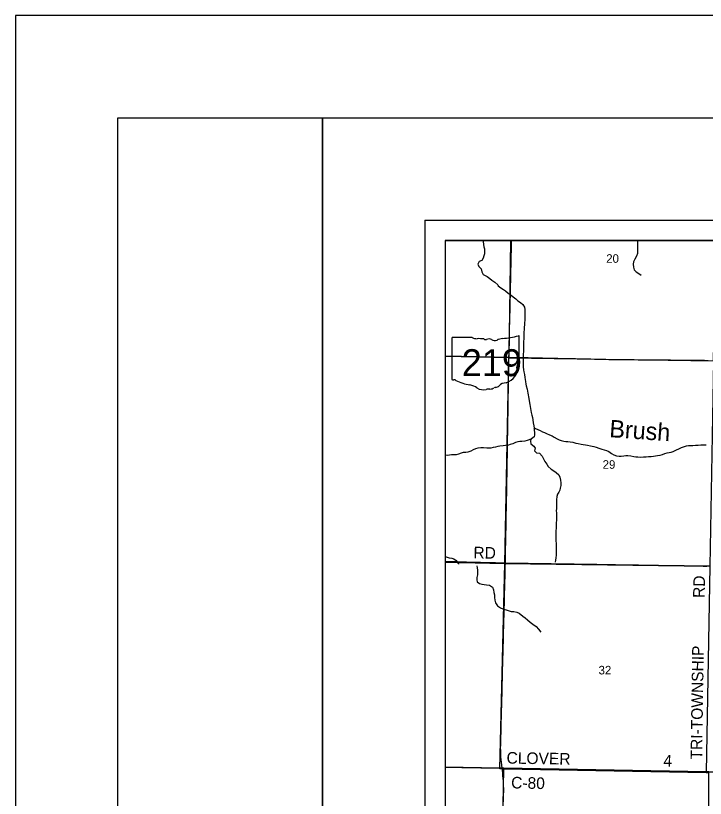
# Model space of a CAD drawing. Extents: x -11.1 to 34, y -3.9 to 22.
# Drawn here: x 0 to 3.372, y 18.172 to 22 of the extents above; entities that cross this region are included whole.
import ezdxf

# ---------------------------------------------------------------- set-up
doc = ezdxf.new("R2010")
doc.units = 0
for name, color, linetype in [('GM_X_Corporation', 7, 'Continuous'), ('GM_X_County_Road', 7, 'Continuous'), ('GM_X_County_Road_Text', 7, 'Continuous'), ('GM_X_Minor_River', 7, 'Continuous'), ('GM_X_Minor_River_Text', 7, 'Continuous'), ('GM_X_Section_Text', 7, 'Continuous'), ('GM_X_State_Location', 7, 'Continuous'), ('GM_X_State_Route', 7, 'Continuous'), ('GM_X_State_Shield', 7, 'Continuous'), ('GM_X_Township_Road_Text', 7, 'Continuous'), ('SH_Border', 7, 'Continuous'), ('SH_Cut_Line', 7, 'Continuous'), ('SH_Data', 7, 'Continuous')]:
    doc.layers.add(name, color=color, linetype=linetype)

msp = doc.modelspace()

# ---------------------------------------------------------------- linework, layer by layer
at = {"layer": 'GM_X_Corporation'}
for points in [[(8.9, 20.9), (2.1, 20.9), (2.1, 14.1), (7.332, 14.1)], [(7.452, 20.9), (2.1, 20.9), (2.1, 18.3243), (2.3663, 18.3195), (2.386, 18.3192), (3.3765, 18.301), (3.3885, 18.301), (4.3933, 18.2849), (4.8079, 18.2783), (5.3973, 18.2661), (6.2873, 18.2553), (6.3214, 18.2549), (6.5234, 18.2515), (7.399, 18.2383)], [(7.399, 18.2383), (6.5234, 18.2515), (6.3214, 18.2549), (6.2873, 18.2553), (5.3973, 18.2661), (4.8079, 18.2783), (4.3933, 18.2849), (3.3885, 18.301), (3.3765, 18.301), (2.386, 18.3192), (2.3663, 18.3195), (2.1, 18.3243), (2.1, 15.3106)]]:
    msp.add_lwpolyline(points, dxfattribs=at)
for points in [[(3.4231, 20.9), (2.4189, 20.9), (2.4116, 20.3267), (3.4122, 20.3123)], [(2.1, 20.3321), (2.1, 19.327), (2.3914, 19.3197), (2.4116, 20.3267)], [(3.4122, 20.3123), (3.3936, 19.3072), (2.3914, 19.3197), (2.4116, 20.3267)], [(2.3914, 19.3197), (3.3936, 19.3072), (3.3764, 18.2972), (2.3861, 18.3151), (2.3675, 18.3155)], [(2.3861, 18.3151), (3.3764, 18.2972), (3.3877, 18.2966), (3.3852, 17.301), (2.3686, 17.3282)]]:
    msp.add_lwpolyline(points, close=True, dxfattribs=at)
at = {"layer": 'GM_X_County_Road'}
for points in [[(2.1, 19.3307), (2.104, 19.3306), (2.1226, 19.3301), (2.1413, 19.3296), (2.1544, 19.3293), (2.1675, 19.3289), (2.1862, 19.3284), (2.2048, 19.3279), (2.22, 19.3275), (2.2351, 19.3271), (2.2538, 19.3267), (2.2724, 19.3263), (2.291, 19.3259), (2.3096, 19.3255), (2.3282, 19.3251), (2.346, 19.3246), (2.3637, 19.3242), (2.3758, 19.3238), (2.3879, 19.3235), (2.3944, 19.3229), (2.413, 19.3227), (2.4317, 19.3224), (2.4503, 19.3221), (2.4689, 19.3218), (2.4876, 19.3215), (2.5062, 19.3213), (2.5249, 19.321), (2.5435, 19.3207), (2.5621, 19.3204), (2.5808, 19.3201), (2.5994, 19.3199), (2.6181, 19.3196), (2.6367, 19.3193), (2.6554, 19.319), (2.674, 19.3187), (2.6926, 19.3185), (2.7113, 19.3182), (2.7299, 19.3179), (2.7486, 19.3176), (2.7672, 19.3173), (2.7858, 19.317), (2.8045, 19.3168), (2.8231, 19.3165), (2.8418, 19.3162), (2.8604, 19.3159), (2.8781, 19.3156), (2.8958, 19.3154), (2.9144, 19.3151), (2.933, 19.3148), (2.9517, 19.3145), (2.9703, 19.3142), (2.989, 19.3139), (3.0076, 19.3136), (3.0263, 19.3133), (3.0449, 19.313), (3.0635, 19.3127), (3.0822, 19.3124), (3.1008, 19.3121), (3.1195, 19.3118), (3.1381, 19.3115), (3.1567, 19.3112), (3.1754, 19.3109), (3.194, 19.3106), (3.2127, 19.3103), (3.2313, 19.31), (3.2499, 19.3097), (3.2686, 19.3094), (3.2872, 19.3091), (3.3059, 19.3088), (3.3245, 19.3085), (3.3431, 19.3082), (3.3618, 19.3079), (3.3795, 19.3076)], [(2.1, 18.3245), (2.1071, 18.3243), (2.1257, 18.324), (2.1443, 18.3237), (2.163, 18.3234), (2.1816, 18.3231), (2.2003, 18.3227), (2.2189, 18.3224), (2.2376, 18.3221), (2.2562, 18.3218), (2.2748, 18.3215), (2.2935, 18.3211), (2.3121, 18.3208), (2.3308, 18.3205), (2.3494, 18.3202), (2.3639, 18.3199), (2.3785, 18.3197), (2.3971, 18.3193), (2.4158, 18.319), (2.4344, 18.3186), (2.453, 18.3183), (2.4717, 18.3179), (2.4903, 18.3175), (2.5089, 18.3172), (2.5276, 18.3168), (2.5462, 18.3165), (2.5648, 18.3161), (2.5835, 18.3158), (2.6021, 18.3154), (2.6207, 18.3151), (2.6394, 18.3147), (2.658, 18.3144), (2.6766, 18.314), (2.6953, 18.3137), (2.7139, 18.3133), (2.7325, 18.313), (2.7512, 18.3126), (2.7698, 18.3123), (2.7885, 18.3119), (2.8071, 18.3116), (2.8257, 18.3112), (2.8444, 18.3109), (2.8585, 18.3106), (2.8726, 18.3103), (2.8913, 18.31), (2.9099, 18.3096), (2.9285, 18.3093), (2.9472, 18.3089), (2.9658, 18.3085), (2.9844, 18.3082), (3.0031, 18.3078), (3.0217, 18.3075), (3.0403, 18.3071), (3.059, 18.3067), (3.0776, 18.3064), (3.0963, 18.306), (3.1149, 18.3056), (3.1335, 18.3053), (3.1522, 18.3049), (3.1708, 18.3045), (3.1894, 18.3042), (3.2081, 18.3038), (3.2267, 18.3035), (3.2453, 18.3031), (3.264, 18.3027), (3.2826, 18.3024), (3.3012, 18.302), (3.3199, 18.3016), (3.3385, 18.3013), (3.3561, 18.3009), (3.3736, 18.3006)]]:
    msp.add_lwpolyline(points, dxfattribs=at)
at = {"layer": 'GM_X_Minor_River'}
msp.add_line((3.0391, 20.9), (3.0399, 20.8925), dxfattribs=at)
for points in [[(2.2862, 20.9), (2.2864, 20.896), (2.2879, 20.8812), (2.2895, 20.8697), (2.2915, 20.8598), (2.293, 20.845), (2.2927, 20.8347), (2.2883, 20.8246), (2.2853, 20.8132), (2.2789, 20.802), (2.2659, 20.7978), (2.2602, 20.7846), (2.2641, 20.7735), (2.2752, 20.7611), (2.2786, 20.7469), (2.2851, 20.7342), (2.2952, 20.7287), (2.305, 20.7235), (2.3177, 20.7148), (2.3282, 20.7069), (2.342, 20.6963), (2.3568, 20.683)], [(3.0399, 20.8925), (3.04, 20.8822), (3.0397, 20.8727), (3.0395, 20.8628), (3.0399, 20.8499), (3.0399, 20.8358), (3.0358, 20.823), (3.0266, 20.8085), (3.0213, 20.7953), (3.0191, 20.784), (3.0199, 20.7691), (3.0245, 20.7561), (3.0337, 20.7464), (3.0461, 20.7384), (3.0576, 20.7301)], [(2.3568, 20.683), (2.3594, 20.6786), (2.3717, 20.6684), (2.3848, 20.6609), (2.3957, 20.6535), (2.4083, 20.6433), (2.4225, 20.6324), (2.4326, 20.6253), (2.4456, 20.6144), (2.4557, 20.6058), (2.468, 20.5964), (2.4799, 20.587), (2.4872, 20.574), (2.4888, 20.5625), (2.4901, 20.55), (2.4902, 20.5393), (2.4897, 20.5192), (2.4891, 20.5082), (2.4881, 20.4984), (2.4872, 20.4889), (2.4861, 20.4748), (2.4858, 20.4642), (2.4852, 20.4521), (2.4846, 20.4407), (2.4839, 20.4305), (2.4831, 20.3948), (2.4833, 20.3838), (2.4833, 20.3686), (2.4826, 20.3564), (2.482, 20.3451), (2.4813, 20.3318), (2.4811, 20.3196), (2.4815, 20.3056), (2.4812, 20.2938), (2.4814, 20.2828), (2.4829, 20.2683), (2.485, 20.2576), (2.4877, 20.2447), (2.4897, 20.2306), (2.4906, 20.2203), (2.4919, 20.2108), (2.4946, 20.1982), (2.4967, 20.1886), (2.5001, 20.173), (2.5025, 20.1634), (2.5046, 20.1528), (2.5085, 20.1268), (2.5106, 20.1162), (2.5136, 20.0982), (2.5156, 20.0879), (2.5169, 20.0777), (2.519, 20.0681), (2.521, 20.0582), (2.5238, 20.046), (2.5262, 20.0345), (2.5282, 20.0238), (2.5309, 20.0082), (2.5332, 19.9941), (2.5345, 19.9819), (2.535, 19.972), (2.5359, 19.961), (2.5364, 19.9492), (2.535, 19.9394), (2.5227, 19.9298), (2.5108, 19.9255), (2.5001, 19.9223), (2.4887, 19.9192), (2.475, 19.9176), (2.4655, 19.9174), (2.4548, 19.9157), (2.4434, 19.9122), (2.4303, 19.9064), (2.4185, 19.9025), (2.409, 19.8997), (2.3949, 19.897), (2.3827, 19.8961), (2.3664, 19.8949), (2.3568, 19.8932), (2.3458, 19.8901), (2.3354, 19.8869), (2.3233, 19.8845), (2.3138, 19.8836), (2.3031, 19.8838), (2.288, 19.8853), (2.2751, 19.8856), (2.2603, 19.8852), (2.2481, 19.8816), (2.237, 19.8769), (2.2254, 19.8704), (2.2113, 19.8646), (2.2003, 19.8637), (2.1885, 19.8632), (2.1774, 19.86), (2.1659, 19.8557), (2.153, 19.8526), (2.142, 19.8517), (2.1313, 19.8512), (2.121, 19.8495), (2.1108, 19.849), (2.1, 19.8496)], [(2.5341, 19.9857), (2.5413, 19.9806), (2.5522, 19.9758), (2.5646, 19.9702), (2.5758, 19.9643), (2.586, 19.9603), (2.5957, 19.9562), (2.6092, 19.9502), (2.6231, 19.9442), (2.6329, 19.9387), (2.6467, 19.93), (2.658, 19.9245), (2.6678, 19.9216), (2.6799, 19.919), (2.6897, 19.9173), (2.7003, 19.9163), (2.7113, 19.9153), (2.7237, 19.9131), (2.7392, 19.9093), (2.7505, 19.9068), (2.7641, 19.9038), (2.7743, 19.9021), (2.786, 19.9003), (2.7962, 19.8985), (2.8102, 19.8959), (2.8264, 19.8918), (2.8377, 19.8892), (2.8517, 19.8851), (2.866, 19.8802), (2.8777, 19.8762), (2.8882, 19.8725), (2.8998, 19.8677), (2.9129, 19.8579), (2.9245, 19.8512), (2.9373, 19.8475), (2.9502, 19.8449), (2.9612, 19.8454), (2.973, 19.8474), (2.9829, 19.8483), (2.9927, 19.8485), (3.0071, 19.8474), (3.0222, 19.8432), (3.0328, 19.8419), (3.0426, 19.8416), (3.057, 19.8409), (3.0703, 19.8418), (3.0825, 19.8422), (3.0939, 19.8431), (3.1068, 19.8436), (3.1178, 19.8445), (3.1277, 19.8461), (3.138, 19.8478), (3.151, 19.8509), (3.1624, 19.8541), (3.1743, 19.858), (3.1849, 19.8608), (3.1949, 19.8636), (3.2044, 19.8653), (3.2151, 19.868), (3.2316, 19.8764), (3.2431, 19.8818), (3.2546, 19.8869), (3.2653, 19.8912), (3.2794, 19.8951), (3.2889, 19.8967), (3.2992, 19.8976), (3.3102, 19.8978), (3.3239, 19.8986), (3.3372, 19.8994), (3.3501, 19.9006), (3.3649, 19.9007), (3.3755, 19.9001)], [(2.5183, 19.9282), (2.5164, 19.9193), (2.5191, 19.9048), (2.5332, 19.8942), (2.5406, 19.8846), (2.5365, 19.871), (2.5462, 19.862), (2.5617, 19.8594), (2.5739, 19.8455), (2.579, 19.8358), (2.5877, 19.8197), (2.5965, 19.8058), (2.6042, 19.7954), (2.6179, 19.7818), (2.6307, 19.7735), (2.6422, 19.7653), (2.6556, 19.7532), (2.6607, 19.7425), (2.6645, 19.7279), (2.6654, 19.715), (2.6651, 19.7013), (2.6625, 19.6892), (2.66, 19.6794), (2.6549, 19.6697), (2.6497, 19.6592), (2.6453, 19.6475), (2.6438, 19.6319), (2.6438, 19.6148), (2.6435, 19.6054), (2.6435, 19.5886), (2.6433, 19.5776), (2.6435, 19.5681), (2.6436, 19.5583), (2.6436, 19.5423), (2.6438, 19.5309), (2.6431, 19.5211), (2.6421, 19.5074), (2.6411, 19.4653), (2.6417, 19.4554), (2.6414, 19.444), (2.6415, 19.4307), (2.642, 19.4185), (2.642, 19.4052), (2.6418, 19.3954), (2.642, 19.3718), (2.6418, 19.3616), (2.6407, 19.3475), (2.6397, 19.3373), (2.638, 19.3271)], [(2.1, 19.3549), (2.1192, 19.3483), (2.1328, 19.3461), (2.143, 19.3432), (2.1542, 19.3349), (2.1604, 19.3249), (2.1691, 19.3193)], [(2.2548, 19.3084), (2.2561, 19.2988), (2.2574, 19.287), (2.2587, 19.2771), (2.2576, 19.2646), (2.2551, 19.2514), (2.2552, 19.2408), (2.2565, 19.2305), (2.2677, 19.2222), (2.2786, 19.2193), (2.29, 19.2183), (2.3028, 19.2165), (2.3164, 19.2139), (2.331, 19.2049), (2.3364, 19.1911), (2.3384, 19.1785), (2.3404, 19.1667), (2.3416, 19.1537), (2.3425, 19.1412), (2.3456, 19.1271), (2.3563, 19.1135), (2.3705, 19.1037), (2.3817, 19.0989), (2.4077, 19.0896), (2.422, 19.0855), (2.4364, 19.0855), (2.4508, 19.0821), (2.462, 19.0777), (2.4791, 19.0625), (2.4915, 19.0539), (2.5022, 19.0441), (2.5157, 19.0332), (2.5284, 19.0242), (2.5444, 19.0117), (2.5566, 18.9985), (2.5677, 18.9849)]]:
    msp.add_lwpolyline(points, dxfattribs=at)
at = {"layer": 'GM_X_State_Route'}
for points in [[(2.4117, 20.329), (2.4121, 20.3477), (2.4126, 20.3663), (2.413, 20.3849), (2.4134, 20.4036), (2.4139, 20.4222), (2.4143, 20.4409), (2.4147, 20.4595), (2.4151, 20.4781), (2.4156, 20.4968), (2.416, 20.5154), (2.4164, 20.534), (2.4169, 20.5527), (2.4173, 20.5713), (2.4177, 20.5899), (2.4181, 20.6086), (2.4186, 20.6272), (2.419, 20.6458), (2.4194, 20.6645), (2.4198, 20.6831), (2.4203, 20.7017), (2.4207, 20.7204), (2.4211, 20.739), (2.4215, 20.7576), (2.422, 20.7763), (2.4224, 20.7949), (2.4228, 20.8125), (2.4232, 20.8301), (2.4235, 20.8488), (2.4237, 20.8674), (2.424, 20.8861), (2.4242, 20.9)], [(2.1, 20.3354), (2.1026, 20.3354), (2.1135, 20.3351), (2.1322, 20.3348), (2.1468, 20.3345), (2.1613, 20.3342), (2.18, 20.3338), (2.1986, 20.3334), (2.2173, 20.333), (2.2304, 20.3328), (2.2435, 20.3325), (2.2621, 20.3321), (2.2725, 20.3319), (2.283, 20.3317), (2.3016, 20.3313), (2.3203, 20.3309), (2.3389, 20.3305), (2.3575, 20.3302), (2.3762, 20.3298), (2.3939, 20.3294), (2.4117, 20.329), (2.4304, 20.3286), (2.449, 20.3283), (2.4676, 20.3279), (2.4771, 20.3277), (2.4865, 20.3275), (2.5051, 20.3271), (2.5238, 20.3267), (2.5424, 20.3263), (2.561, 20.3259), (2.5761, 20.3256), (2.5911, 20.3253), (2.6098, 20.3249), (2.6284, 20.3245), (2.6397, 20.3243), (2.6509, 20.3241), (2.6623, 20.3238), (2.6809, 20.3234), (2.6996, 20.3231), (2.7182, 20.3227), (2.7369, 20.3223), (2.7555, 20.3219), (2.7741, 20.3215), (2.7928, 20.3211), (2.8114, 20.3207), (2.83, 20.3203), (2.8487, 20.32), (2.8673, 20.3196), (2.8859, 20.3192), (2.8994, 20.3189), (2.9129, 20.3186), (2.9315, 20.3184), (2.9501, 20.3182), (2.9688, 20.3181), (2.9874, 20.3179), (3.0061, 20.3177), (3.0247, 20.3175), (3.0434, 20.3173), (3.062, 20.3171), (3.0806, 20.317), (3.0993, 20.3168), (3.1179, 20.3166), (3.1366, 20.3164), (3.1503, 20.3163), (3.164, 20.3161), (3.1826, 20.316), (3.2012, 20.3158), (3.2199, 20.3156), (3.2385, 20.3154), (3.2572, 20.3152), (3.2758, 20.315), (3.2919, 20.3149), (3.3081, 20.3147), (3.3267, 20.3145), (3.3453, 20.3144), (3.3564, 20.3143), (3.3674, 20.3141), (3.3861, 20.314)], [(2.3785, 18.3197), (2.3769, 18.3339), (2.3752, 18.3482), (2.374, 18.3615), (2.3727, 18.3748), (2.3721, 18.3849), (2.3716, 18.3951), (2.3714, 18.4059), (2.3712, 18.4167), (2.3717, 18.4354), (2.3722, 18.454), (2.3726, 18.4726), (2.3731, 18.4913), (2.3736, 18.5099), (2.374, 18.5285), (2.3745, 18.5472), (2.375, 18.5658), (2.3754, 18.5844), (2.3759, 18.6031), (2.3764, 18.6217), (2.3769, 18.6403), (2.3773, 18.659), (2.3778, 18.6776), (2.3783, 18.6962), (2.3787, 18.7149), (2.3792, 18.7335), (2.3797, 18.7522), (2.3801, 18.7708), (2.3806, 18.7894), (2.381, 18.8061), (2.3814, 18.8229), (2.3819, 18.8415), (2.3824, 18.8601), (2.3829, 18.8788), (2.3834, 18.8974), (2.3839, 18.916), (2.3843, 18.9347), (2.3848, 18.9533), (2.3853, 18.9719), (2.3858, 18.9906), (2.3863, 19.0092), (2.3868, 19.0278), (2.3872, 19.0465), (2.3877, 19.0651), (2.3882, 19.0838), (2.3887, 19.1024), (2.3892, 19.121), (2.3896, 19.1397), (2.3901, 19.1583), (2.3906, 19.1769), (2.3911, 19.1956), (2.3916, 19.2142), (2.392, 19.2328), (2.3925, 19.2515), (2.393, 19.2701), (2.3935, 19.2887), (2.3939, 19.3058), (2.3944, 19.3229), (2.3947, 19.3416), (2.3951, 19.3602), (2.3954, 19.3788), (2.3957, 19.3975), (2.3961, 19.4161), (2.3964, 19.4347), (2.3968, 19.4534), (2.3971, 19.472), (2.3975, 19.4906), (2.3978, 19.5093), (2.3982, 19.5279), (2.3985, 19.5465), (2.3988, 19.5652), (2.3992, 19.5838), (2.3995, 19.6025), (2.3999, 19.6211), (2.4002, 19.6397), (2.4006, 19.6584), (2.4009, 19.677), (2.4013, 19.6956), (2.4016, 19.7143), (2.4019, 19.7329), (2.4023, 19.7515), (2.4026, 19.7702), (2.403, 19.7888), (2.4033, 19.8068), (2.4037, 19.8248), (2.4039, 19.8434), (2.4042, 19.8621), (2.4045, 19.8807), (2.4048, 19.8994), (2.4051, 19.918), (2.4054, 19.9366), (2.4057, 19.9553), (2.406, 19.9739), (2.4063, 19.9926), (2.4066, 20.0112), (2.4069, 20.0298), (2.4072, 20.0485), (2.4075, 20.0671), (2.4078, 20.0858), (2.4081, 20.1044), (2.4084, 20.1231), (2.4087, 20.1417), (2.409, 20.1603), (2.4093, 20.179), (2.4096, 20.1976), (2.4099, 20.2163), (2.4102, 20.2349), (2.4105, 20.2535), (2.4108, 20.2722), (2.4111, 20.2908), (2.4114, 20.3095), (2.4116, 20.3192), (2.4117, 20.329)], [(2.3853, 18.1543), (2.3856, 18.1727), (2.3859, 18.1911), (2.386, 18.2058), (2.386, 18.2205), (2.3859, 18.2326), (2.3857, 18.2448), (2.3848, 18.2567), (2.3839, 18.2685), (2.3826, 18.2824), (2.3813, 18.2963), (2.3799, 18.308), (2.3785, 18.3197)]]:
    msp.add_lwpolyline(points, dxfattribs=at)
at = {"layer": 'GM_X_State_Shield'}
for p, q in [((2.1326, 20.4226), (2.1326, 20.2225)), ((2.2324, 20.426), (2.1359, 20.426)), ((2.4622, 20.3263), (2.4622, 20.431)), ((2.4622, 20.3263), (2.4622, 20.3263))]:
    msp.add_line(p, q, dxfattribs=at)
for centre, major_axis, start_param, end_param in [((2.1364, 20.423), (0.00382, 0), 1.712693, 3.28349), ((2.2554, 20.4493), (0.037, 0), 4.042523, 4.731795), ((2.2677, 20.3137), (0.133, 0), 1.404758, 1.657858), ((2.2978, 20.4241), (0.0107, 0), 3.836095, 5.185415), ((2.3135, 20.4009), (0.0222, 0), 0.950623, 2.079405), ((2.3422, 20.4327), (0.0267, 0), 4.081561, 5.145723), ((2.3894, 20.3649), (0.0703, 0), 1.699011, 2.107814), ((2.3448, 20.6989), (0.3495, 0), 4.814394, 5.042369), ((2.4586, 20.4314), (0.00367, 0), 6.141152, 7.989035), ((2.4754, 20.2825), (0.0248, 0), 2.387724, 3.262537), ((2.4614, 20.3186), (0.00568, 0), 1.883978, 3.671073), ((2.4252, 20.3054), (0.0341, 0), 5.934695, 6.695948), ((2.4583, 20.3259), (0.00393, 0), 5.05454, 6.418171), ((2.3644, 20.2692), (0.0874, 0), 5.101752, 6.440018), ((2.1364, 20.222), (0.00385, 0), 3.00124, 4.508301), ((2.137, 20.2425), (0.0294, 0), 4.665946, 4.897461), ((2.143, 20.2109), (0.0106, 0), 0.519207, 1.627899), ((2.2769, 20.3907), (0.2524, 0), 4.195997, 4.488961), ((2.2016, 20.1326), (0.079, 0), 0.823519, 1.323587), ((2.287, 20.2099), (0.0501, 0), 4.026481, 4.996735), ((2.3196, 20.195), (0.0267, 0), 4.691044, 5.507374), ((2.3438, 20.1756), (0.00752, 0), 1.147584, 2.315152), ((2.3406, 20.2031), (0.0282, 0), 4.937069, 5.64225), ((2.4013, 20.1663), (0.0479, 0), 1.647645, 2.488434), ((2.316, 20.1407), (0.0412, 0), 1.495662, 1.94098)]:
    msp.add_ellipse(centre, major_axis=major_axis, ratio=0.8, start_param=start_param, end_param=end_param, dxfattribs=at)
at = {"layer": 'SH_Border'}
for points in [[(0.5, 21.5), (1.5, 21.5), (1.5, 0.5), (0.5, 0.5)], [(1.5, 21.5), (33.5, 21.5), (33.5, 0.5), (1.5, 0.5)]]:
    msp.add_lwpolyline(points, close=True, dxfattribs=at)
at = {"layer": 'SH_Cut_Line'}
msp.add_lwpolyline([(0, 0), (34, 0), (34, 22), (0, 22)], close=True, dxfattribs=at)
at = {"layer": 'SH_Data'}
for p, q in [((2, 21), (9, 21)), ((2, 21), (2, 14)), ((2.1, 20.9), (2.1, 14.1)), ((2.1, 20.9), (8.9, 20.9))]:
    msp.add_line(p, q, dxfattribs=at)

# ---------------------------------------------------------------- texts
at = {"layer": 'GM_X_County_Road_Text'}
for s, height, rotation, p in [('RD', 0.05682, 358.5184, (2.2374, 19.3459)), ('CLOVER', 0.05682, 358.9677, (2.3998, 18.3417)), ('4', 0.0568, 358.8989, (3.1665, 18.3275)), ('C-80', 0.05682, 358.628, (2.422, 18.2206))]:
    msp.add_text(s, height=height, rotation=rotation, dxfattribs=at).set_placement(p)
at = {"layer": 'GM_X_Minor_River_Text'}
msp.add_text('Brush', height=0.08523, rotation=356.05, dxfattribs=at).set_placement((2.9006, 19.9386))
at = {"layer": 'GM_X_Section_Text'}
for s, p in [('20', (2.8873, 20.7911)), ('29', (2.8698, 19.7836)), ('32', (2.8498, 18.7777))]:
    msp.add_text(s, height=0.04186, rotation=0, dxfattribs=at).set_placement(p)
at = {"layer": 'GM_X_State_Location'}
msp.add_text('219', height=0.000189, rotation=0, dxfattribs=at).set_placement((2.2269, 20.2955))
for s in ['s', 'r']:
    msp.add_text(s, height=0.000189, dxfattribs=at).set_placement((2.2937, 20.3092))
at = {"layer": 'GM_X_State_Shield'}
msp.add_text('219', height=0.13184, dxfattribs=at).set_placement((2.1811, 20.2366))
at = {"layer": 'GM_X_Township_Road_Text'}
for s, height, rotation, p in [('RD', 0.05682, 89.0128, (3.3687, 19.1514)), ('TRI-TOWNSHIP', 0.056818, 89.1306, (3.3562, 18.3613))]:
    msp.add_text(s, height=height, rotation=rotation, dxfattribs=at).set_placement(p)

doc.saveas('drawing.dxf')
